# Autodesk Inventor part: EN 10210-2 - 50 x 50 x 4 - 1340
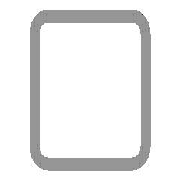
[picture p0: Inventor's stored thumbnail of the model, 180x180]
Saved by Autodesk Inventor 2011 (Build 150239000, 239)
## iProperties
IsCustomPart: 1
Created: 2010-02
Part Number: EN 10210-2 - 50 x 50 x 4 - 1340
Material: Steel, Mild
Description: Tube 50*50*4
Document SubType Name: Modeling
Standard: DIN
Designer: PC
Standard Revision: 1997
Standards Organization: DIN
Language: en-US
Size Designation: 50 x 50 x 4
Categories: <MemberInstance><Categories><Category DisplayName="Structural Shapes" InternalName="089c4875-fa83-4c05-b084-43b9cc11f5ed" Mnemonic="GRDR"><CategoryParameter Dis
Stock Number: 50 x 50 x 4
Density: 7.86 g/cm^3
_CCFamilyMember: 15
_CCFamilyDisplayName: DIN EN 10210-2 (Square) - Tube
_FrameMemberDoc: Frame Member File
_Version: 15.0.0
_GetPNFromCC: 1
G_L: 1340.000 mm
G_W: 50.000 mm
G_H: 50.000 mm
Author: PC
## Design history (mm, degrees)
node "Start plane"
node "End plane"
sketch "Sketch"
  geometry: L1 (-25, -19)-(-25, 19); L2 (-19, 25)-(19, 25); L3 (25, 19)-(25, -19); L4 (19, -25)-(-19, -25); L5 (-19, 21)-(19, 21); L6 (21, 19)-(21, -19); L7 (19, -21)-(-19, -21); L8 (-21, -19)-(-21, 19); L9 (0, 36.74)-(0, -36.74) reference; L10 (-36.74, 0)-(36.74, 0) reference; A1 r 6 centre (-19, -19) between (-25, -19) and (-19, -25); A2 r 6 centre (-19, 19) between (-19, 25) and (-25, 19); A3 r 6 centre (19, 19) between (25, 19) and (19, 25); A4 r 6 centre (19, -19) between (19, -25) and (25, -19); A5 r 2 centre (-19, 19) between (-19, 21) and (-21, 19); A6 r 2 centre (19, 19) between (21, 19) and (19, 21); A7 r 2 centre (19, -19) between (19, -21) and (21, -19); A8 r 2 centre (-19, -19) between (-21, -19) and (-19, -21)
  constraints: 16 end point, 16 point on circle, 8 centre point, 8 tangent, 4 parallel, 3 equal radius, 2 perpendicular, 7 other
  dimensions: "d7" = 6 radius of A1 (= G_IR); "d10" = 50 distance between parallel lines of L2 L4 (= G_H); "d11" = 50 distance between parallel lines of L1 L3 (= G_W); "d12" = 4 distance between parallel lines of L3 L6 (= G_T); "d15" = 25 distance between parallel lines of L2 L10 (= 0.5 x d10); "d16" = 25 distance between parallel lines of L9 L3 (= 0.5 x d11)
extrude "Body" new body sketch "Sketch" stored distance "d3" = 1340 (= G_L); taper "d4" = 0 deg
node "Driven Length"
  sketch "Sketch3"
    geometry: L1 (0, 0)-(10, 0) reference
    constraints: 2 end point, 1 horizontal
  workplane "Work Plane3"
  sketch "Sketch4"
    geometry: L1 (-2, 0)-(12, 0) reference; L2 (-2, 1340)-(12, 1340) reference
    dimensions: "d18" = 1340 distance between parallel lines of L1 L2 (derived)
body "Solid1"
other parameters: "G_W" = 50 [user parameter; used in 1 equation term], "G_H" = 50 [user parameter; used in 1 equation term], "G_T" = 4 [user parameter; used in 1 equation term], "G_IR" = 6 [user parameter; used in 1 equation term], "G_L" = 1340 (= d18) [user parameter; used in 1 equation term], "G_OFFSET_START" = 0 [user parameter; used in 1 equation term], "G_OFFSET_END" = 0 [user parameter; used in 1 equation term], "d13" = 0 (computed from G_OFFSET_START), "d17" = 90 deg
